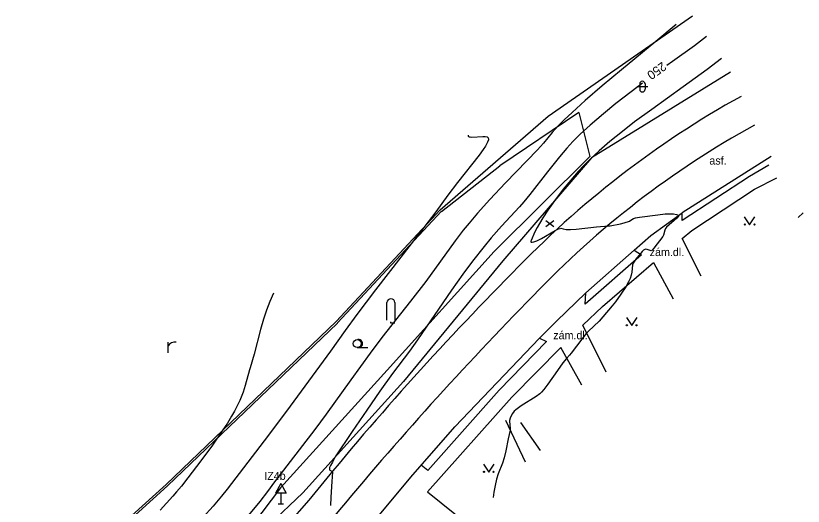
# Model space of a CAD drawing. Extents: x -593772 to -592667, y -1183541 to -1183371.
# Drawn here: x -592740.4 to -592666.6, y -1183486.6 to -1183440.7 of the extents above; entities that cross this region are included whole.
import ezdxf

# ---------------------------------------------------------------- set-up
doc = ezdxf.new("R2010")
doc.units = 0
for name, color, linetype in [('bez obruby', 7, 'Continuous'), ('hlavni vrstevnice', 7, 'Continuous'), ('obruba snizena', 7, 'Continuous'), ('obruba zvysena', 7, 'Continuous'), ('popis ploch', 7, 'Continuous'), ('svisle dopravni znaceni', 7, 'Continuous'), ('terenni hrany', 7, 'Continuous'), ('vodorovne dopravni znaceni', 7, 'Continuous'), ('vrstevnice', 7, 'Continuous'), ('zelen', 7, 'Continuous')]:
    doc.layers.add(name, color=color, linetype=linetype)

msp = doc.modelspace()

# ---------------------------------------------------------------- linework, layer by layer
at = {"layer": 'bez obruby'}
msp.add_line((-592712.97, -1183486.06), (-592720.24, -1183494.25), dxfattribs=at)
for centre, radius, start, end in [((-592628.749, -1183526.995), 90.086, 119.03423, 136.32991), ((-592493.234, -1183663.79), 282.616, 135.24024, 141.03286)]:
    msp.add_arc(centre, radius, start, end, dxfattribs=at)
at = {"layer": 'hlavni vrstevnice'}
for points in [[(-592675.701, -1183442.618), (-592676.85, -1183443.488), (-592678.893, -1183444.966), (-592679.431, -1183445.353)], [(-592681.72, -1183447.007), (-592682.775, -1183447.797), (-592684.194, -1183448.909), (-592685.373, -1183449.872), (-592686.608, -1183450.927), (-592687.532, -1183451.763), (-592688.019, -1183452.232), (-592688.247, -1183452.465), (-592688.805, -1183453.081), (-592689.496, -1183453.904), (-592690.606, -1183455.299), (-592692.275, -1183457.433), (-592692.826, -1183458.101), (-592693.244, -1183458.572), (-592694.923, -1183460.391), (-592695.887, -1183461.481), (-592696.551, -1183462.283), (-592697.623, -1183463.657), (-592698.54, -1183464.889), (-592699.594, -1183466.373), (-592702.774, -1183471.035), (-592703.526, -1183472.086), (-592705.114, -1183474.202), (-592706.314, -1183475.858), (-592707.541, -1183477.613), (-592708.901, -1183479.62), (-592710.487, -1183482.007), (-592710.751, -1183482.493), (-592710.924, -1183482.793), (-592711.013, -1183482.999), (-592711.036, -1183483.114), (-592711.026, -1183483.191), (-592710.992, -1183483.241), (-592710.803, -1183483.34), (-592710.766, -1183483.387), (-592710.755, -1183483.441), (-592710.798, -1183484.313), (-592710.899, -1183485.778), (-592710.919, -1183486.539)]]:
    msp.add_lwpolyline(points, dxfattribs=at)
at = {"layer": 'obruba snizena'}
for p, q in [((-592669.86, -1183454.69), (-592671.69, -1183455.73)), ((-592671.69, -1183455.73), (-592677.98, -1183459.85)), ((-592680.92, -1183461.26), (-592678, -1183459.14)), ((-592677.98, -1183459.85), (-592678, -1183459.14)), ((-592682.5, -1183462.64), (-592680.92, -1183461.26)), ((-592682.5, -1183462.64), (-592681.81, -1183463.07)), ((-592681.81, -1183463.07), (-592687.08, -1183467.69)), ((-592689.75, -1183469.28), (-592687.02, -1183466.64)), ((-592687.08, -1183467.69), (-592687.02, -1183466.64)), ((-592691.35, -1183470.89), (-592689.75, -1183469.28)), ((-592691.35, -1183470.89), (-592690.71, -1183471.2)), ((-592690.71, -1183471.2), (-592695.13, -1183475.75)), ((-592695.13, -1183475.75), (-592701.82, -1183483.27)), ((-592701.82, -1183483.27), (-592702.443, -1183482.787)), ((-592707.93, -1183489.32), (-592703.42, -1183483.9))]:
    msp.add_line(p, q, dxfattribs=at)
at = {"layer": 'obruba zvysena'}
for p, q in [((-592669.66, -1183453.87), (-592678, -1183459.14)), ((-592671.21, -1183456.91), (-592669.13, -1183455.87)), ((-592677.09, -1183460.8), (-592671.21, -1183456.91)), ((-592677.99, -1183461.55), (-592677.09, -1183460.8)), ((-592676.22, -1183465.06), (-592677.99, -1183461.55)), ((-592682.5, -1183462.64), (-592687.02, -1183466.64)), ((-592685.46, -1183467.92), (-592680.68, -1183463.79)), ((-592680.68, -1183463.79), (-592678.83, -1183467.21)), ((-592687.31, -1183469.67), (-592685.46, -1183467.92)), ((-592685.11, -1183474.06), (-592687.31, -1183469.67)), ((-592699.28, -1183479.18), (-592691.35, -1183470.89)), ((-592689.35, -1183471.75), (-592693.96, -1183476.41)), ((-592687.4, -1183475.28), (-592689.35, -1183471.75)), ((-592693.96, -1183476.41), (-592701.85, -1183485.26)), ((-592703.42, -1183483.9), (-592699.28, -1183479.18)), ((-592701.85, -1183485.26), (-592697.99, -1183488.36))]:
    msp.add_line(p, q, dxfattribs=at)
at = {"layer": 'popis ploch'}
for p, q in [((-592682.22, -1183447.32), (-592681.22, -1183447.32)), ((-592681.97, -1183447.07), (-592681.97, -1183447.57)), ((-592681.47, -1183447.07), (-592681.47, -1183447.57)), ((-592672.17, -1183459.51), (-592671.67, -1183460.26)), ((-592671.67, -1183460.26), (-592671.17, -1183459.51)), ((-592705.65, -1183469.2), (-592705.65, -1183467.55)), ((-592704.9, -1183467.55), (-592704.9, -1183469.2)), ((-592683.22, -1183468.95), (-592682.72, -1183469.7)), ((-592682.72, -1183469.7), (-592682.22, -1183468.95)), ((-592726.15, -1183472.26), (-592726.15, -1183471.26)), ((-592708.43, -1183471.76), (-592707.43, -1183471.76)), ((-592696.61, -1183482.67), (-592696.11, -1183483.42)), ((-592696.11, -1183483.42), (-592695.61, -1183482.67))]:
    msp.add_line(p, q, dxfattribs=at)
msp.add_lwpolyline([(-592705.3, -1183469.35), (-592705.3, -1183469.45), (-592704.9, -1183469.45)], dxfattribs=at)
for centre, radius in [((-592672.12, -1183460.235), 0.0559), ((-592671.22, -1183460.235), 0.0559), ((-592683.17, -1183469.675), 0.0559), ((-592682.27, -1183469.675), 0.0559), ((-592708.429, -1183471.386), 0.375), ((-592696.56, -1183483.395), 0.0559), ((-592695.66, -1183483.395), 0.0559)]:
    msp.add_circle(centre, radius, dxfattribs=at)
for centre, radius, start, end in [((-592681.721, -1183447.07), 0.25, 0, 180), ((-592681.721, -1183447.57), 0.25, 180, 0), ((-592708.304, -1183471.386), 0.375, 260.40593, 99.59407), ((-592725.513, -1183471.998), 0.746, 81.32683, 148.70696)]:
    msp.add_arc(centre, radius, start, end, dxfattribs=at)
msp.add_ellipse((-592705.275, -1183467.55), major_axis=(-0.375, 0), ratio=0.935414, start_param=3.141593, end_param=6.283185, dxfattribs=at)
at = {"layer": 'svisle dopravni znaceni'}
for p, q in [((-592690.755, -1183460.431), (-592690.005, -1183459.869)), ((-592690.755, -1183459.869), (-592690.005, -1183460.431)), ((-592715.58, -1183484.5), (-592716.08, -1183485.4)), ((-592715.58, -1183484.5), (-592715.08, -1183485.4)), ((-592715.08, -1183485.4), (-592716.08, -1183485.4)), ((-592715.58, -1183485.4), (-592715.58, -1183486.4)), ((-592715.83, -1183486.4), (-592715.33, -1183486.4))]:
    msp.add_line(p, q, dxfattribs=at)
at = {"layer": 'terenni hrany'}
for p, q in [((-592690.55, -1183450.08), (-592677.01, -1183440.68)), ((-592673.45, -1183445.95), (-592686.49, -1183453.99)), ((-592700.67, -1183458.86), (-592690.55, -1183450.08)), ((-592686.49, -1183453.99), (-592694.8, -1183463.62)), ((-592710.41, -1183469.32), (-592700.67, -1183458.86)), ((-592694.8, -1183463.62), (-592704.08, -1183474.93)), ((-592726.34, -1183484.57), (-592710.41, -1183469.32)), ((-592704.08, -1183474.93), (-592713.54, -1183485.37)), ((-592694.55, -1183478.56), (-592692.69, -1183482.45)), ((-592693.15, -1183478.77), (-592691.3, -1183481.39)), ((-592740.42, -1183497.27), (-592726.34, -1183484.57)), ((-592713.54, -1183485.37), (-592721.37, -1183492.81))]:
    msp.add_line(p, q, dxfattribs=at)
at = {"layer": 'vodorovne dopravni znaceni'}
for centre, radius, start, end in [((-592630.039, -1183525.73), 85.39, 118.82573, 136.47149), ((-592458.669, -1183696.357), 327.203, 135.4759, 140.36347)]:
    msp.add_arc(centre, radius, start, end, dxfattribs=at)
at = {"layer": 'vrstevnice'}
for points in [[(-592678.537, -1183441.494), (-592680.468, -1183443.096), (-592683.688, -1183445.743), (-592685.486, -1183447.256), (-592687.071, -1183448.631), (-592688.302, -1183449.738), (-592689.032, -1183450.422), (-592689.599, -1183450.984), (-592690.156, -1183451.623), (-592690.988, -1183452.618), (-592691.542, -1183453.232), (-592694.53, -1183456.317), (-592696.02, -1183457.903), (-592697.172, -1183459.178), (-592697.958, -1183460.092), (-592698.501, -1183460.763), (-592699.262, -1183461.767), (-592702.007, -1183465.573), (-592703.428, -1183467.409), (-592706.13, -1183470.828), (-592707.23, -1183472.278), (-592709.044, -1183474.795), (-592711.333, -1183478.001), (-592712.407, -1183479.442), (-592716.168, -1183484.346), (-592716.83, -1183485.227), (-592717.566, -1183486.178), (-592718.764, -1183487.66)], [(-592674.304, -1183444.686), (-592675.652, -1183445.702), (-592677.899, -1183447.33), (-592680.847, -1183449.449), (-592682.44, -1183450.631), (-592683.583, -1183451.512), (-592684.768, -1183452.471), (-592685.76, -1183453.323), (-592686.617, -1183454.113), (-592687.177, -1183454.674), (-592687.734, -1183455.27), (-592688.426, -1183456.067), (-592689.125, -1183456.929), (-592689.957, -1183458.023), (-592690.565, -1183458.884), (-592691.039, -1183459.606), (-592691.354, -1183460.125), (-592691.581, -1183460.528), (-592691.786, -1183460.928), (-592692.148, -1183461.735), (-592692.169, -1183461.805), (-592692.16, -1183461.861), (-592692.121, -1183461.892), (-592692.044, -1183461.899), (-592691.897, -1183461.865), (-592691.61, -1183461.751), (-592691.175, -1183461.53), (-592689.891, -1183460.806), (-592689.567, -1183460.648), (-592689.421, -1183460.598), (-592689.349, -1183460.591), (-592689.13, -1183460.649), (-592688.85, -1183460.689), (-592688.45, -1183460.697), (-592687.927, -1183460.665), (-592686.01, -1183460.438), (-592684.851, -1183460.365), (-592684.724, -1183460.347), (-592683.78, -1183460.157), (-592683.421, -1183460.066), (-592682.938, -1183459.909), (-592682.791, -1183459.832), (-592682.536, -1183459.668), (-592682.44, -1183459.627), (-592682.366, -1183459.606), (-592681.978, -1183459.532), (-592680.268, -1183459.312), (-592679.576, -1183459.246), (-592679.082, -1183459.229), (-592678.789, -1183459.244), (-592678.535, -1183459.282), (-592678.309, -1183459.354), (-592678.291, -1183459.376), (-592678.328, -1183459.447), (-592678.501, -1183459.635), (-592679.445, -1183460.484), (-592679.546, -1183460.602), (-592679.624, -1183460.757), (-592679.742, -1183461.222), (-592679.811, -1183461.358), (-592680.631, -1183462.439), (-592680.803, -1183462.645), (-592680.842, -1183462.673), (-592680.902, -1183462.69), (-592680.987, -1183462.68), (-592681.28, -1183462.567), (-592681.387, -1183462.555), (-592681.488, -1183462.576), (-592681.602, -1183462.635), (-592681.725, -1183462.752), (-592681.955, -1183463.035), (-592682.268, -1183463.397), (-592682.469, -1183463.66), (-592682.583, -1183463.858), (-592682.635, -1183464.019), (-592682.707, -1183464.7), (-592682.768, -1183464.993), (-592682.867, -1183465.287), (-592683.011, -1183465.6), (-592683.281, -1183466.064), (-592683.746, -1183466.773), (-592684.245, -1183467.468), (-592684.545, -1183467.854), (-592685.413, -1183468.896), (-592685.774, -1183469.285), (-592686.762, -1183470.213), (-592686.971, -1183470.441), (-592687.398, -1183470.978), (-592688.376, -1183472.292), (-592688.532, -1183472.468), (-592688.838, -1183472.785), (-592689.171, -1183473.2), (-592689.673, -1183473.899), (-592690.56, -1183475.184), (-592690.937, -1183475.678), (-592691.164, -1183475.942), (-592691.339, -1183476.099), (-592691.681, -1183476.345), (-592693.07, -1183477.223), (-592693.57, -1183477.58), (-592693.721, -1183477.723), (-592693.876, -1183477.923), (-592694.006, -1183478.149), (-592694.101, -1183478.375), (-592694.151, -1183478.594), (-592694.153, -1183478.643), (-592694.088, -1183479.348), (-592694.095, -1183479.489), (-592694.276, -1183480.314), (-592694.501, -1183481.44), (-592694.669, -1183482.096), (-592694.833, -1183482.598), (-592695.225, -1183483.593), (-592695.379, -1183484.083), (-592695.522, -1183484.677), (-592695.633, -1183485.291), (-592695.708, -1183485.815)], [(-592698.024, -1183451.877), (-592698.028, -1183451.946), (-592697.999, -1183451.981), (-592697.954, -1183452.007), (-592697.856, -1183452.03), (-592697.697, -1183452.038), (-592696.676, -1183451.984), (-592696.451, -1183451.994), (-592696.255, -1183452.036), (-592696.167, -1183452.112), (-592696.151, -1183452.135), (-592696.139, -1183452.204), (-592696.141, -1183452.288), (-592696.218, -1183452.535), (-592696.416, -1183452.894), (-592696.62, -1183453.199), (-592697.013, -1183453.732), (-592699.044, -1183456.307), (-592699.935, -1183457.481), (-592701.082, -1183459.054), (-592702.185, -1183460.507), (-592706.727, -1183466.361), (-592708.464, -1183468.659), (-592709.557, -1183470.161), (-592710.923, -1183472.082), (-592715.06, -1183477.712), (-592717.143, -1183480.493), (-592720.61, -1183485.021), (-592721.142, -1183485.692), (-592721.932, -1183486.617), (-592722.88, -1183487.662)], [(-592666.647, -1183459.146), (-592667.111, -1183459.591)], [(-592716.283, -1183466.651), (-592716.615, -1183467.431), (-592716.926, -1183468.257), (-592717.199, -1183469.085), (-592717.479, -1183470.064), (-592718.084, -1183472.379), (-592718.457, -1183473.643), (-592718.517, -1183473.84), (-592718.919, -1183475.32), (-592719.119, -1183475.925), (-592719.242, -1183476.25), (-592719.441, -1183476.72), (-592719.639, -1183477.14), (-592719.934, -1183477.705), (-592720.198, -1183478.175), (-592720.596, -1183478.829), (-592721.018, -1183479.479), (-592721.998, -1183480.896), (-592723.084, -1183482.383), (-592724.297, -1183483.965), (-592724.904, -1183484.737), (-592725.349, -1183485.273), (-592725.695, -1183485.665), (-592726.892, -1183486.98)]]:
    msp.add_lwpolyline(points, dxfattribs=at)
at = {"layer": 'zelen'}
for p, q in [((-592687.67, -1183449.74), (-592695.08, -1183454.74)), ((-592687.67, -1183449.74), (-592686.641, -1183453.859)), ((-592686.641, -1183453.859), (-592695.59, -1183462.76)), ((-592700.539, -1183459.011), (-592695.08, -1183454.74)), ((-592710.264, -1183469.456), (-592700.524, -1183458.996)), ((-592705.64, -1183473.87), (-592695.59, -1183462.76)), ((-592726.204, -1183484.717), (-592710.272, -1183469.464)), ((-592715.63, -1183484.91), (-592705.64, -1183473.87)), ((-592740.301, -1183497.432), (-592726.204, -1183484.717)), ((-592715.63, -1183484.91), (-592721.508, -1183492.665))]:
    msp.add_line(p, q, dxfattribs=at)

# ---------------------------------------------------------------- texts
at = {"layer": 'hlavni vrstevnice'}
msp.add_text('250', height=0.8351, rotation=215.81264, dxfattribs=at).set_placement((-592679.856, -1183444.959))
at = {"layer": 'popis ploch'}
for s, p in [('asf.', (-592675.443, -1183454.62)), ('zám.dl.', (-592681.035, -1183463.19)), ('zám.dl.', (-592690.065, -1183470.98))]:
    msp.add_text(s, height=0.75, dxfattribs=at).set_placement(p)
at = {"layer": 'svisle dopravni znaceni'}
msp.add_text('IZ4b', height=0.75, dxfattribs=at).set_placement((-592717.14, -1183484.15))

doc.saveas('drawing.dxf')
